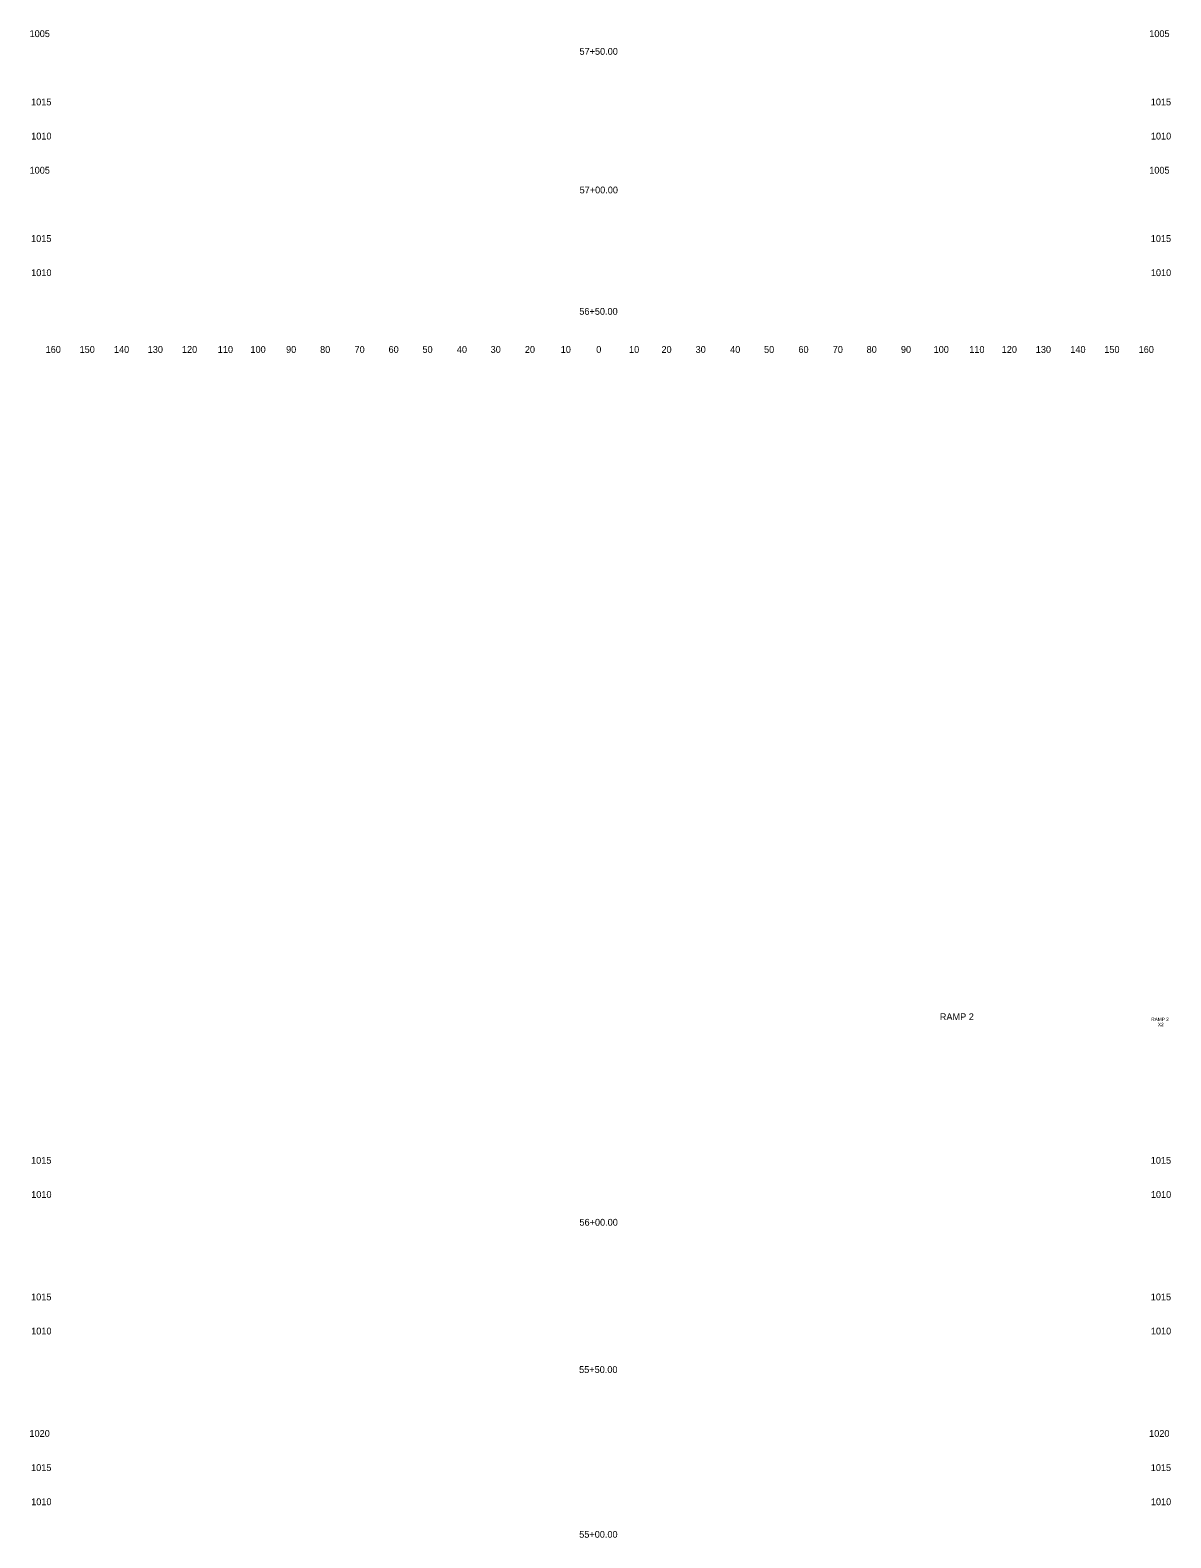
# Model space of a CAD drawing. Extents: x 4994 to 5328, y 4997 to 8804.
# Drawn here: x 4993.6 to 5327.5, y 5450.4 to 5892 of the extents above; entities that cross this region are included whole.
import ezdxf

# ---------------------------------------------------------------- set-up
doc = ezdxf.new("R2010")
doc.units = 0
for name, color, linetype in [('RD_SHT_ID', 7, 'Continuous'), ('RD_XS_TX_Offset', 7, 'Continuous'), ('RD_XS_TX_Station', 7, 'Continuous')]:
    doc.layers.add(name, color=color, linetype=linetype)

msp = doc.modelspace()

# ---------------------------------------------------------------- texts
at = {"layer": 'RD_SHT_ID'}
for s, height, p in [('RAMP 2', 2, (5259.89, 5602.06)), ('RAMP 2', 1, (5321.78, 5601.8)), ('X2', 1, (5323.74, 5600.3))]:
    msp.add_text(s, height=height, dxfattribs=at).set_placement(p)
at = {"layer": 'RD_XS_TX_Offset'}
for s, p in [('1005', (4993.4, 5890)), ('1005', (5321.2, 5890)), ('1015', (4993.85, 5870)), ('1015', (5321.65, 5870)), ('1010', (4993.88, 5860)), ('1010', (5321.68, 5860)), ('1005', (4993.4, 5850)), ('1005', (5321.2, 5850)), ('1015', (4993.85, 5830)), ('1015', (5321.65, 5830)), ('1010', (4993.88, 5820)), ('1010', (5321.68, 5820)), ('160', (4998.1, 5797.5)), ('150', (5008.04, 5797.5)), ('140', (5018.1, 5797.5)), ('130', (5027.99, 5797.5)), ('120', (5038.01, 5797.5)), ('110', (5048.51, 5797.5)), ('100', (5058.07, 5797.5)), ('90', (5068.5, 5797.5)), ('80', (5078.46, 5797.5)), ('70', (5088.54, 5797.5)), ('60', (5098.5, 5797.5)), ('50', (5108.43, 5797.5)), ('40', (5118.5, 5797.5)), ('30', (5128.39, 5797.5)), ('20', (5138.4, 5797.5)), ('10', (5148.91, 5797.5)), ('0', (5159.3, 5797.5)), ('0', (5159.3, 5797.5)), ('10', (5168.91, 5797.5)), ('20', (5178.4, 5797.5)), ('30', (5188.39, 5797.5)), ('40', (5198.5, 5797.5)), ('50', (5208.43, 5797.5)), ('60', (5218.5, 5797.5)), ('70', (5228.54, 5797.5)), ('80', (5238.46, 5797.5)), ('90', (5248.5, 5797.5)), ('100', (5258.07, 5797.5)), ('110', (5268.51, 5797.5)), ('120', (5278.01, 5797.5)), ('130', (5287.99, 5797.5)), ('140', (5298.1, 5797.5)), ('150', (5308.04, 5797.5)), ('160', (5318.1, 5797.5)), ('1015', (4993.85, 5560)), ('1015', (5321.65, 5560)), ('1010', (4993.88, 5550)), ('1010', (5321.68, 5550)), ('1015', (4993.85, 5520)), ('1015', (5321.65, 5520)), ('1010', (4993.88, 5510)), ('1010', (5321.68, 5510)), ('1020', (4993.37, 5480)), ('1020', (5321.17, 5480)), ('1015', (4993.85, 5470)), ('1015', (5321.65, 5470)), ('1010', (4993.88, 5460)), ('1010', (5321.68, 5460))]:
    msp.add_text(s, height=2, dxfattribs=at).set_placement(p)
at = {"layer": 'RD_XS_TX_Station'}
for s, p in [('57+50.00', (5154.4, 5884.81)), ('57+00.00', (5154.43, 5844.22)), ('56+50.00', (5154.35, 5808.66)), ('56+00.00', (5154.39, 5541.86)), ('55+50.00', (5154.29, 5498.72)), ('55+00.00', (5154.32, 5450.46))]:
    msp.add_text(s, height=2, dxfattribs=at).set_placement(p)

doc.saveas('drawing.dxf')
